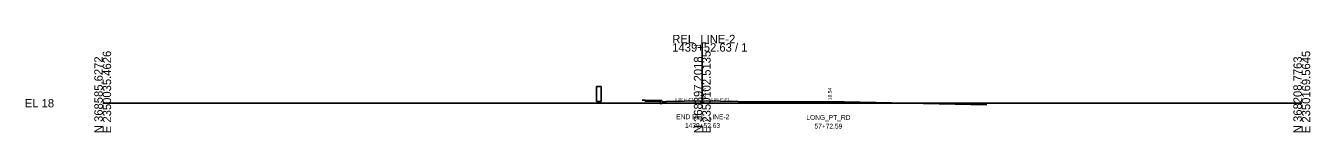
# Model space of a CAD drawing. Extents: x -26 to 2349775, y -10 to 368669.
# Drawn here: x 2374.3 to 2802.8, y -9.7 to 22.8 of the extents above; entities that cross this region are included whole.
import ezdxf

# ---------------------------------------------------------------- set-up
doc = ezdxf.new("R2010")
doc.units = 0
for name, color, linetype in [('RD_GPK_XS_Cell', 7, 'Continuous'), ('RD_XS_CurbBase', 7, 'Continuous'), ('RD_XS_CurbFront', 7, 'Continuous'), ('RD_XS_CurbTop', 7, 'Continuous'), ('RD_XS_EarthShd', 7, 'Continuous'), ('RD_XS_MedBWall', 7, 'Continuous'), ('RD_XS_Pave', 7, 'Continuous'), ('RD_XS_PaveShd', 7, 'Continuous'), ('RD_XS_SW', 7, 'Continuous'), ('RD_XS_SWbase', 7, 'Continuous'), ('RD_XS_SWfront', 7, 'Continuous'), ('RD_XS_TX_Elev_PR', 7, 'Continuous'), ('RD_XS_TX_Slope', 7, 'Continuous'), ('RD_XS_TX_Station', 7, 'Continuous'), ('RD_XS_TX_TOC', 7, 'Continuous')]:
    doc.layers.add(name, color=color, linetype=linetype)

msp = doc.modelspace()

# ---------------------------------------------------------------- linework, layer by layer
at = {"layer": 'RD_GPK_XS_Cell'}
for p, q in [((2600, 0), (2600, 20)), ((2400, 0), (2600, 0)), ((2600, 0), (2800, 0))]:
    msp.add_line(p, q, dxfattribs=at)
at = {"layer": 'RD_XS_CurbBase'}
for p, q in [((2586, 0.59), (2586, -0.07)), ((2586.5, -0.07), (2588, 0.01)), ((2586, -0.07), (2586.5, -0.07))]:
    msp.add_line(p, q, dxfattribs=at)
at = {"layer": 'RD_XS_CurbFront'}
msp.add_line((2588, 0.01), (2588, 0.51), dxfattribs=at)
at = {"layer": 'RD_XS_CurbTop'}
for p, q in [((2586.5, 0.93), (2586, 0.93)), ((2586.58, 0.43), (2586.5, 0.93)), ((2588, 0.51), (2586.58, 0.43)), ((2588, 0.53), (2588, 0.51))]:
    msp.add_line(p, q, dxfattribs=at)
at = {"layer": 'RD_XS_EarthShd'}
msp.add_line((2581, 1.03), (2580, 1.05), dxfattribs=at)
at = {"layer": 'RD_XS_MedBWall'}
for p, q in [((2564.75, 5.58), (2564.75, 0.58)), ((2566.25, 5.58), (2564.75, 5.58)), ((2566.25, 0.58), (2566.25, 5.58)), ((2566.25, 0.58), (2564.75, 0.58))]:
    msp.add_line(p, q, dxfattribs=at)
at = {"layer": 'RD_XS_Pave'}
for p, q in [((2600, 0.77), (2588, 0.53)), ((2612, 0.53), (2600, 0.77)), ((2642, 0.54), (2618, 0.45)), ((2642, 0.54), (2694.94, -0.52))]:
    msp.add_line(p, q, dxfattribs=at)
at = {"layer": 'RD_XS_PaveShd'}
msp.add_line((2618, 0.45), (2612, 0.53), dxfattribs=at)
at = {"layer": 'RD_XS_SW'}
msp.add_line((2586, 0.93), (2581, 1.03), dxfattribs=at)
at = {"layer": 'RD_XS_SWbase'}
for p, q in [((2581, 1.03), (2581, 0.69)), ((2581, 0.69), (2586, 0.59))]:
    msp.add_line(p, q, dxfattribs=at)
at = {"layer": 'RD_XS_SWfront'}
msp.add_line((2586, 0.93), (2586, 0.59), dxfattribs=at)

# ---------------------------------------------------------------- texts
at = {"layer": 'RD_GPK_XS_Cell'}
for s, p in [('REL_LINE-2', (2590, 20)), ('1439+52.63 / 1', (2590, 17.2)), ('EL 18', (2374, -1.4))]:
    msp.add_text(s, height=2.8, dxfattribs=at).set_placement(p)
for s, p in [('E 2350035.4626', (2402.8, -10)), ('E 2350102.5135', (2602.8, -10)), ('E 2350169.5645', (2802.8, -10)), ('N 368585.6272', (2400, -10)), ('N 368397.2018', (2600, -10)), ('N 368208.7763', (2800, -10))]:
    msp.add_text(s, height=2.8, rotation=90, dxfattribs=at).set_placement(p)
at = {"layer": 'RD_XS_TX_Elev_PR'}
for s, p in [(' 18.77', (2601.2, 0.77)), (' 18.54', (2643.2, 0.54))]:
    msp.add_text(s, height=1.2, rotation=90, dxfattribs=at).set_placement(p)
at = {"layer": 'RD_XS_TX_Slope'}
for rotation, p in [(1.1458, (2590.97, 0.84)), (358.8542, (2602.98, 0.96))]:
    msp.add_text('0.020 FT./FT.', height=0.75, rotation=rotation, dxfattribs=at).set_placement(p)
at = {"layer": 'RD_XS_TX_Station'}
for s, p in [('END REL_LINE-2', (2591.33, -5.33)), ('LONG_PT_RD', (2634.72, -5.56)), ('1439+52.63', (2594.23, -8.23)), ('57+72.59', (2637.44, -8.46))]:
    msp.add_text(s, height=1.6, dxfattribs=at).set_placement(p)
at = {"layer": 'RD_XS_TX_TOC'}
msp.add_text('TOCLT', height=0.05, dxfattribs=at).set_placement((2586.55, 0.88))

doc.saveas('drawing.dxf')
